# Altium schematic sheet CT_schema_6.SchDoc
size 411 x 401 mm
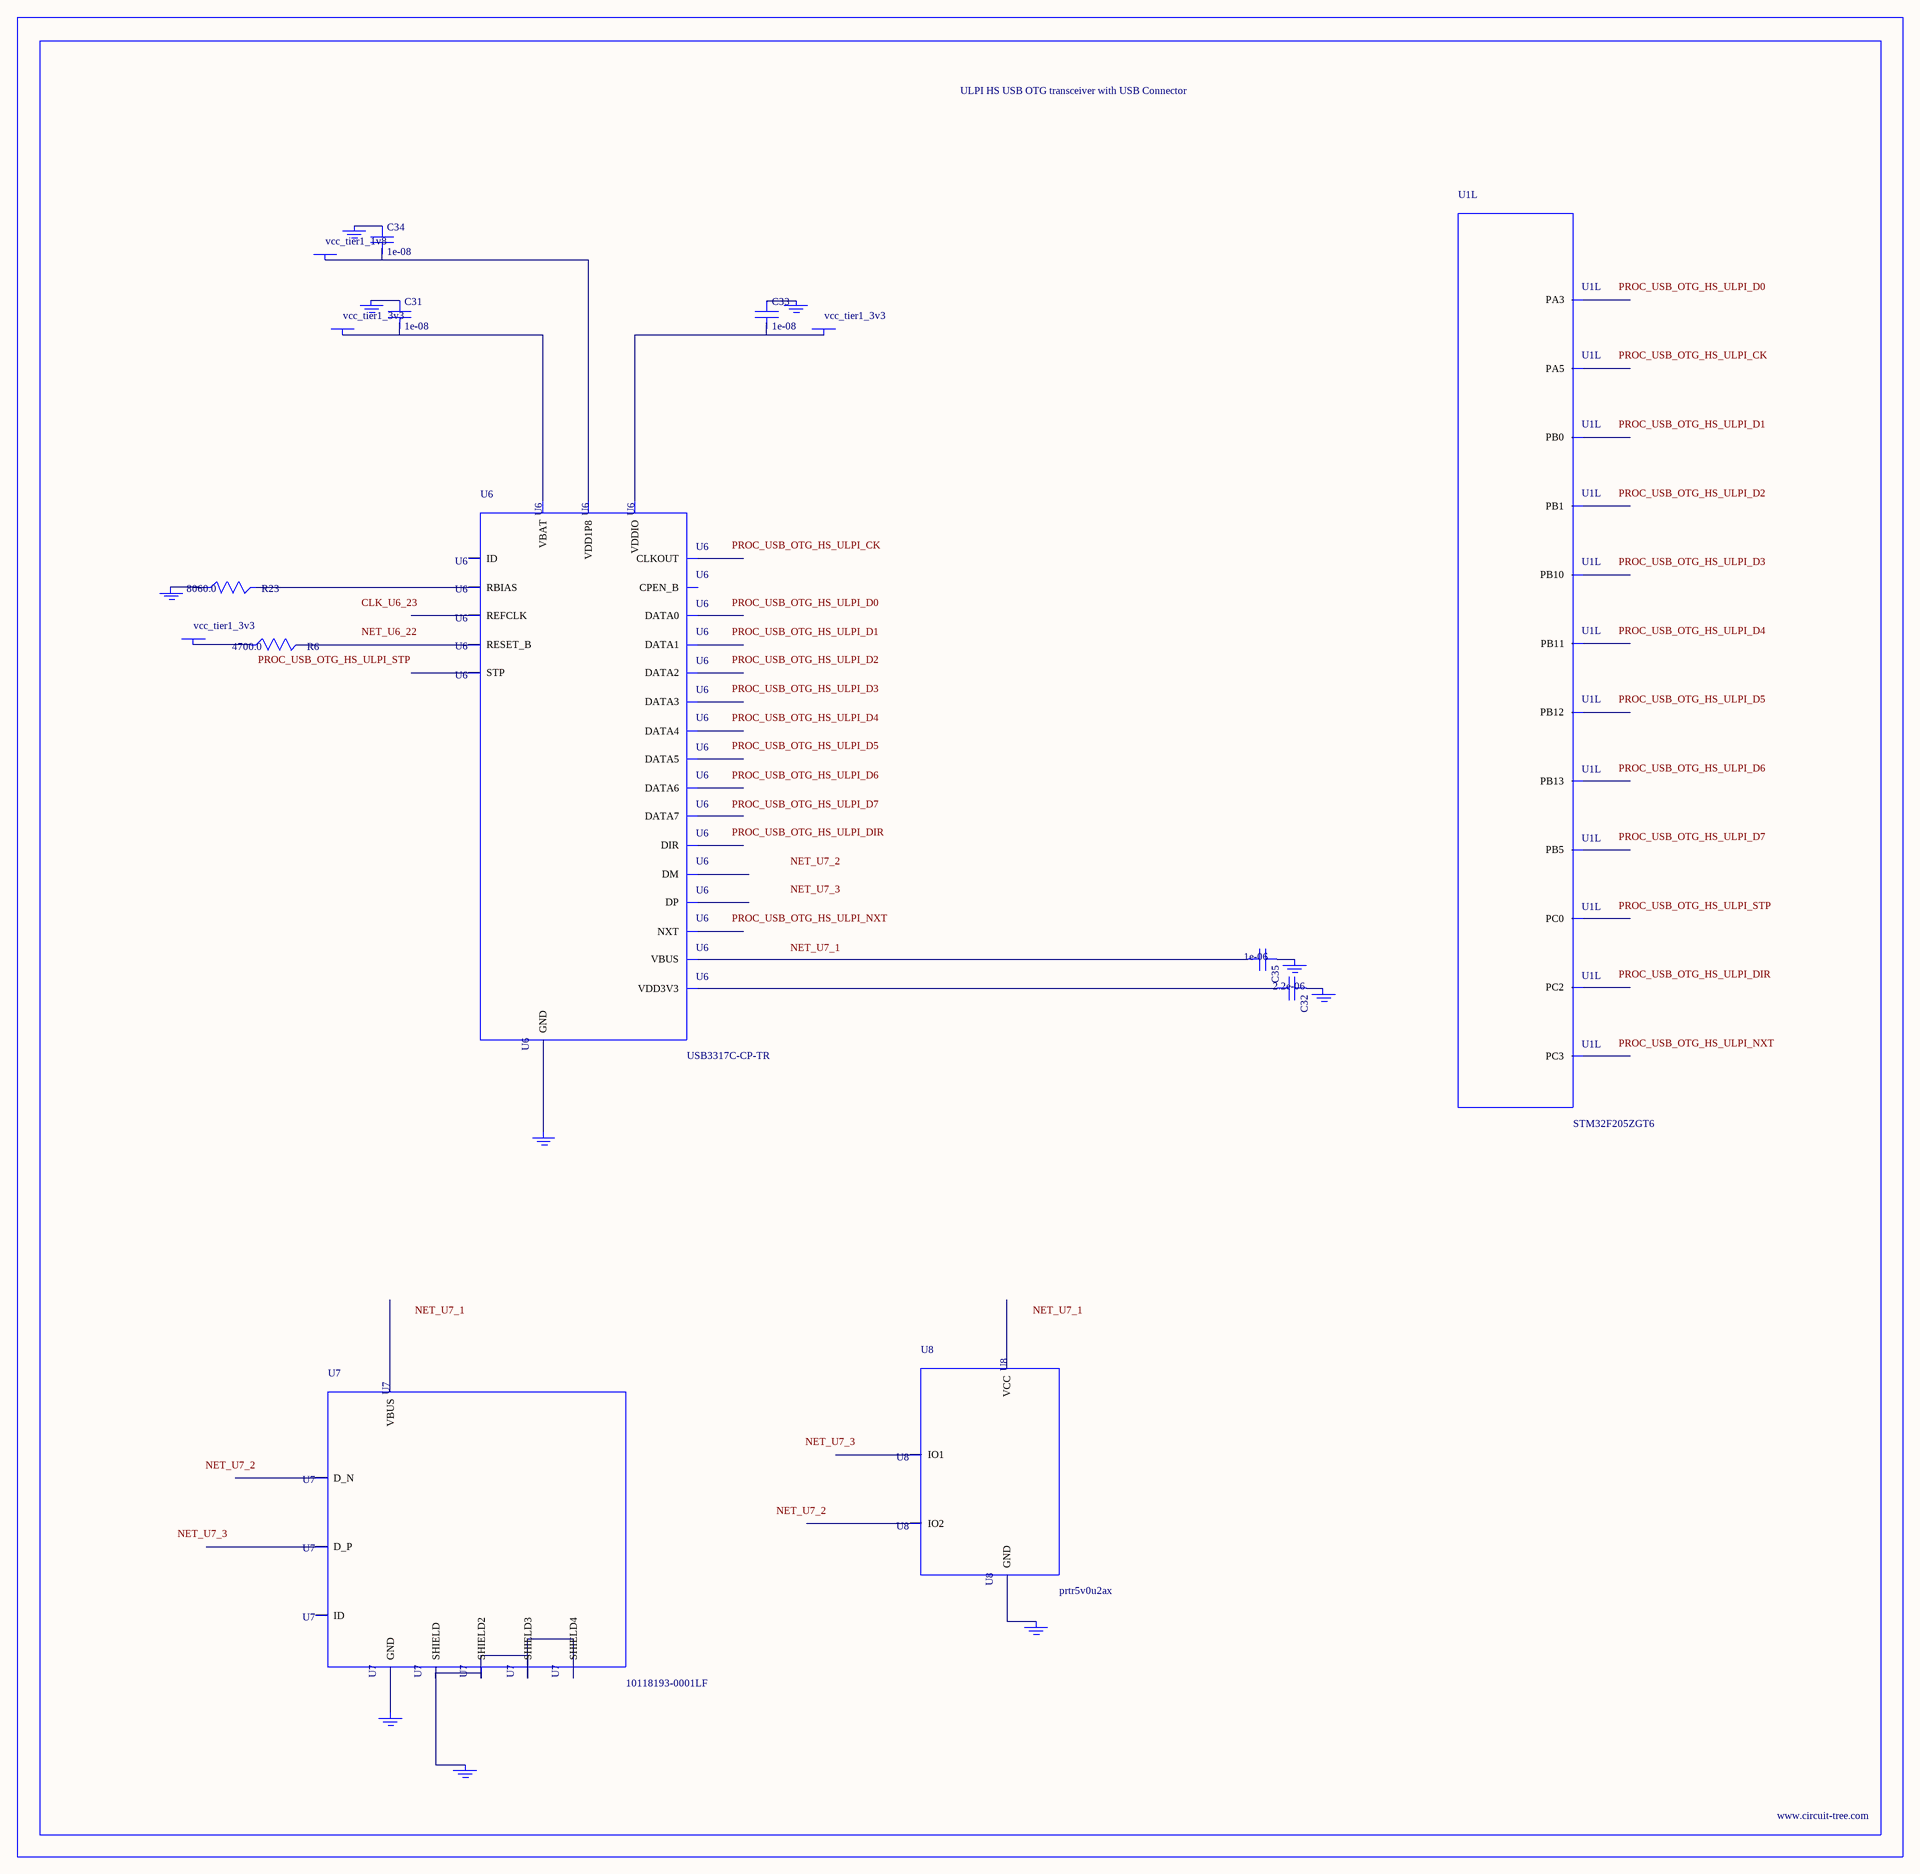
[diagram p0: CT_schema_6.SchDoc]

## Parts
BORDER5  (no value)
C31  1e-08  [C0402]
C32  2.2e-06  [C0603]
C33  1e-08  [C0402]
C34  1e-08  [C0402]
C35  1e-06  [C0603]
GND_INSTANCE_5_0  (no value)
GND_INSTANCE_5_1  (no value)
GND_INSTANCE_5_2  (no value)
GND_INSTANCE_5_3  (no value)
GND_INSTANCE_5_4  (no value)
GND_INSTANCE_5_5  (no value)
GND_INSTANCE_5_6  (no value)
GND_INSTANCE_5_7  (no value)
GND_INSTANCE_5_8  (no value)
GND_INSTANCE_5_9  (no value)
POWER_INSTANCE_5_0  vcc_tier1_3v3
POWER_INSTANCE_5_1  vcc_tier1_3v3
POWER_INSTANCE_5_2  vcc_tier1_1v8
POWER_INSTANCE_5_3  vcc_tier1_3v3
R6  4700.0  [R0603]
R23  8060.0  [R0603]
U1  STM32F205ZGT6  [LQFP144]  (part L of 12)
U6  USB3317C-CP-TR  [QFN-24]
U7  10118193-0001LF  [FCI_10118193-0001LF]
U8  prtr5v0u2ax  [SOT143B]

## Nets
NetC31_1: C31.1 GND_INSTANCE_5_1.0(GND)
NetC31_2: C31.2 POWER_INSTANCE_5_0.0(PWR) U6.3(VBAT)
NetC32_1: C32.1 GND_INSTANCE_5_2.0(GND)
NetC32_2: C32.2 U6.4(VDD3V3)
NetC33_1: C33.1 GND_INSTANCE_5_3.0(GND)
NetC33_2: C33.2 POWER_INSTANCE_5_1.0(PWR) U6.17(VDDIO)
NetC34_1: C34.1 GND_INSTANCE_5_4.0(GND)
NetC34_2: C34.2 POWER_INSTANCE_5_2.0(PWR) U6.21(VDD1P8)
NetC35_1: C35.1 GND_INSTANCE_5_0.0(GND)
NetC35_2: C35.2 U6.2(VBUS)
NetGND_INSTANCE_5_5_0: GND_INSTANCE_5_5.0(GND) R23.1
NetGND_INSTANCE_5_6_0: GND_INSTANCE_5_6.0(GND) U6.25(GND)
NetGND_INSTANCE_5_7_0: GND_INSTANCE_5_7.0(GND) U7.6(SHIELD) U7.7(SHIELD2) U7.8(SHIELD3) U7.9(SHIELD4)
NetGND_INSTANCE_5_8_0: GND_INSTANCE_5_8.0(GND) U7.5(GND)
NetGND_INSTANCE_5_9_0: GND_INSTANCE_5_9.0(GND) U8.1(GND)
NetPOWER_INSTANCE_5_3_0: POWER_INSTANCE_5_3.0(PWR) R6.1
NetR6_2: R6.2 U6.22(RESET_B)
NetR23_2: R23.2 U6.24(RBIAS)

Not connected (* = marked no-connect by the designer): U1 26(PC0) 28(PC2) 29(PC3) 37(PA3) 41(PA5) 46(PB0) 47(PB1) 69(PB10) 70(PB11) 73(PB12) 74(PB13) 135(PB5); U6 1(ID) 5(DM) 6(DP) 7(CPEN_B) 8(DATA7) 9(DATA6) 10(DATA5) 11(DATA4) 12(CLKOUT) 13(DATA3) 14(DATA2) 15(DATA1) 16(DATA0) 18(NXT) 19(DIR) 20(STP) 23(REFCLK); U7 1(VBUS) 2(D_N) 3(D_P) 4(ID); U8 2(IO1) 3(IO2) 4(VCC)

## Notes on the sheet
- Labels drawn without touching a wire or pin: CLK_U6_23, NET_U6_22, NET_U7_1, NET_U7_2, NET_U7_3, PROC_USB_OTG_HS_ULPI_CK, PROC_USB_OTG_HS_ULPI_D0, PROC_USB_OTG_HS_ULPI_D1, PROC_USB_OTG_HS_ULPI_D2, PROC_USB_OTG_HS_ULPI_D3, PROC_USB_OTG_HS_ULPI_D4, PROC_USB_OTG_HS_ULPI_D5, PROC_USB_OTG_HS_ULPI_D6, PROC_USB_OTG_HS_ULPI_D7, PROC_USB_OTG_HS_ULPI_DIR, PROC_USB_OTG_HS_ULPI_NXT, PROC_USB_OTG_HS_ULPI_STP

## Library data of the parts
BORDER5 = BORDER_PAGE5
C31 C33 C34 = C0402C103K3RAC
C32 = C0603C225K8RACTU
C35 = C0603C105K3RACTU
GND_INSTANCE_5_0-GND_INSTANCE_5_9 = GND
POWER_INSTANCE_5_0-POWER_INSTANCE_5_3 = PWR
R6 = RC0603JR-074K7L
R23 = ERJ-3EKF8061V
